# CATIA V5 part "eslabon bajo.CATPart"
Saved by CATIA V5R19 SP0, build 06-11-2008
Part number: eslabon bajo
Material "Dull Blue": density 7860 kg/m3, Young's modulus 2e+11 Pa, Poisson ratio 0.266
Bounding box of the stored display mesh (mm): x 215.134 to 253.234, y -414.1 to 363.3, z 11108.335 to 11348.985
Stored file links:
  E:\Luis\Dropbox\3DIT\Parking\planos\cat 3 dit park8\Cadena\eslabon bajo.CATPart
  E:\Luis\Dropbox\3DIT\Parking\planos\cat 3 dit park8\Cadena\Eslabon de Cadena.........................................CATProduct
  E:\Luis\Dropbox\3DIT\Parking\planos\cat 3 dit park8\Cadena\ensamble unico eslabon.CATProduct
  E:\Luis\Dropbox\3DIT\Parking\planos\cat 3 dit park8\Cadena\Eslabon Bajo Completo.CATProduct
  E:\Luis\Dropbox\3DIT\Parking\planos\cat 3 dit park8\Cadena\EslabonCompleto.CATProduct
  C:\Program Files (x86)\Dassault Systemes\B19\intel_a\startup\materials\Catalog.CATMaterial
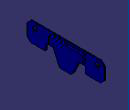
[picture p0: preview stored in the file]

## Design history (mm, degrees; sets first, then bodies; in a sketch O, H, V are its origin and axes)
External parameters (linked from other documents)
  External.p = 625
  External.b1 = 63.5
  External.b2 = 50.8
  External.d2 = 38.1
  External.g = 50.8
Body1 (main body), material "Dull Blue"
  DatumSurface1
  DatumCurve1 to DatumCurve18
  Sketch1 on face of DatumSurface1, origin (253.2342, 0, 0), H (0, -1, 0), V (0, 0, 1)
    line L1 (25.4, 11348.9854) -> (414.1, 11348.9854)
    line L2 (414.1, 11348.9854) -> (414.1, 11158.4854)
    line L3 (223.6, 11228.3354) -> (25.4, 11228.3354)
    point P1 (414.1, 11348.9854)
    point P2 (414.1, 11158.4854)
    line L4 (223.6, 11228.3354) -> (223.6, 11158.4854)
    line L5 (223.6, 11158.4854) -> (414.1, 11158.4854)
    line L6 (414.1, 11158.4854) -> (414.1, 11158.4854)
    point P3 (223.6, 11158.4854)
    point P4 (414.1, 11158.4854)
    construction line L7 (414.1, 11348.9854) -> (223.6, 11158.4854)
    point P5 (223.6, 11228.3354)
    construction line L8 (25.4, 11348.9854) -> (25.4, 11078.9054)
    point P6 (25.4, 11348.9854)
    point P8 (25.4, 11228.3354)
    point P9 (-363.3, 11348.9854)
    point P10 (-363.3, 11158.4854)
    point P11 (-172.8, 11158.4854)
    point P12 (-363.3, 11158.4854)
    construction line L9 (-363.3, 11348.9854) -> (-172.8, 11158.4854)
    point P13 (-172.8, 11228.3354)
    point P14 (25.4, 11348.9854)
    point P15 (25.4, 11228.3354)
    line L10 (25.4, 11348.9854) -> (-363.3, 11348.9854)
    line L11 (-363.3, 11348.9854) -> (-363.3, 11158.4854)
    line L12 (-172.8, 11228.3354) -> (25.4, 11228.3354)
    line L13 (-172.8, 11228.3354) -> (-172.8, 11158.4854)
    line L14 (-172.8, 11158.4854) -> (-363.3, 11158.4854)
    line L15 (-363.3, 11158.4854) -> (-363.3, 11158.4854)
    circle A1 centre (-287.1, 11298.1854) radius 19.05
    circle A2 centre (337.9, 11298.1854) radius 19.05
    point P16 (-287.1, 11298.1854)
    point P17 (337.9, 11298.1854)
    construction line L16 (337.9, 11298.1854) -> (-287.1, 11298.1854)
    radius A2 = 19.05 {= External.d2 /2000}
    distance A2 L2 = 57.15 {= Sketch1.distance(L11 A1)}
    distance A1 L3 = 50.8 {= Sketch1.distance(P17 L1)}
    angle L7 L5 = 45
    length L5 = 190.5 {= External.d2 *5/1000}
    length L11 = 190.5 {= Sketch1.length(L5)}
    distance L11 A1 = 57.15 {= External.d2 *1.5/1000}
    radius A1 = 19.05 {= External.d2/2 /1000}
    distance P16 L8 = 312.5 {= External.p /2000}
    distance P2 H = 11158.4854
    distance L11 V = 363.3
    distance P17 L8 = 312.5 (reference)
    distance P17 L1 = 50.8 {= External.g /1000}
    horizontal: L1 H, L3 H, L5 H, L16 H
    vertical: L2 V, L4 V, L6 V, L8 V
    coincidence: L8 P8
    symmetry: P1 P9 L8, P2 P10 L8, P3 P11 L8, P4 P12 L8, L7 L9 L8, P5 P13 L8, P6 P14 L8, P8 P15 L8, L1 L10 L8, L2 L11 L8, L3 L12 L8, L4 L13 L8, L5 L14 L8, L6 L15 L8
    concentricity: P16 A1, P17 A2
  Pad1: profile Sketch1, direction (-1, 0, 0), length 38.1, opposite side length -25.4
  DatumCurve19 to DatumCurve31
  Sketch2 on start face of Pad1, origin (227.8342, 0, 0), H (0, 1, 0), V (0, 0, 1)
    point P1 (0, 11108.3354)
    line L1 (0, 11108.3354) -> (60, 11108.3354)
    point P2 (60, 11108.3354)
    line L2 (60, 11108.3354) -> (123.6615, 11247.2304)
    point P3 (115, 11228.3329)
    line L3 (123.6615, 11247.2304) -> (123.6615, 11329.9354)
    point P4 (123.6615, 11329.9354)
    line L4 (123.6615, 11329.9354) -> (0, 11329.9354)
    point P5 (0, 11329.9354)
    construction line L5 (0, 11463.76) -> (0, 11058.4)
    point P6 (0, 11463.76)
    reference projected line E1 (-273.1, 11348.9854) -> (273.1, 11348.9854) from edge [start face of Pad1 | face of Pad1 from Sketch1.L1]
    reference projected line E2 (-593.6177, 11109.2854) -> (-745.0129, 11109.2854) from edge of DatumCurve19
    reference projected line E3 (-832.0978, 10989.2854) -> (-876.0554, 10989.2854) from edge of DatumCurve20
    reference projected line E4 (273.1, 11228.3354) -> (-273.1, 11228.3354) from edge [start face of Pad1 | face of Pad1 from Sketch1.L3]
    reference projected arc E5 centre (-1007.0978, 11084.2854) radius 25 from (-984.3712, 11094.7017) to (-1007.0978, 11109.2854) ccw from edge of DatumCurve23
    reference projected arc E6 centre (-745.0129, 11084.2854) radius 25 from (-745.0129, 11109.2854) to (-767.7395, 11094.7017) ccw from edge of DatumCurve24
    point P12 (-745.0129, 11084.2854)
    point P13 (-1007.0978, 11084.2854)
    reference projected line E7 (-767.7395, 11094.7017) -> (-809.3712, 11003.869) from edge of DatumCurve25
    reference projected line E8 (-593.6177, 11109.2854) -> (-745.0129, 11109.2854) from edge of DatumCurve26
    reference projected line E9 (-942.7395, 11003.869) -> (-984.3712, 11094.7017) from edge of DatumCurve27
    reference projected line E10 (-1007.0978, 11109.2854) -> (-1158.4931, 11109.2854) from edge of DatumCurve28
    construction line L6 (-809.3712, 11003.869) -> (-730.157, 11176.7)
    point P22 (-730.157, 11176.7)
    construction line L7 (-637.19, 11109.2854) -> (-761.0554, 11109.2854)
    point P23 (-637.19, 11109.2854)
    construction line L8 (-1092.08, 11109.2854) -> (-1006.3433, 11109.2854)
    point P24 (-1092.08, 11109.2854)
    construction line L9 (-990.62, 11108.3354) -> (-1126.2427, 11116.5297)
    point P25 (-990.62, 11108.3354)
    point P27 (-761.0554, 11109.2854)
    point P28 (-1006.3433, 11109.2854)
    reference projected line E11 (-832.0978, 10989.2854) -> (-876.0554, 10989.2854) from edge of DatumCurve29
    construction line L10 (-1019.9583, 11172.3462) -> (-916.076, 10945.6939)
    point P29 (-1019.9583, 11172.3462)
    construction line L11 (-788.5554, 11049.2854) -> (-845.87, 10950.31)
    point P31 (-788.5554, 11049.2854)
    construction line L12 (-788.5554, 11049.2854) -> (-836.0348, 10945.6939)
    point P33 (-836.0348, 10945.6939)
    construction line L13 (-836.0348, 10945.6939) -> (-916.076, 10945.6939)
    point P34 (-836.0348, 10945.6939)
    reference projected line E12 (-832.0978, 10989.2854) -> (-876.0554, 10989.2854) from edge of DatumCurve30
    construction line L14 (-974.5584, 10989.2854) -> (-936.0554, 10989.2854)
    point P37 (-974.5584, 10989.2854)
    point P38 (-936.0554, 10989.2854)
    construction line L15 (-876.0554, 10989.2854) -> (-816.0554, 10989.2854)
    point P39 (-816.0554, 10989.2854)
    reference projected circle E13 centre (-641.0554, 11209.2854) radius 12.7 from edge of DatumCurve31
    point P40 (-641.0554, 11209.2854)
    reference projected circle E14 centre (-337.9, 11298.1854) radius 19.05 from edge [face of Pad1 from Sketch1.A2 | start face of Pad1]
    point P41 (-337.9, 11298.1854)
    point P42 (0, 11329.9354)
    point P43 (-123.6615, 11329.9354)
    line L16 (-123.6615, 11329.9354) -> (0, 11329.9354)
    line L17 (-123.6615, 11247.2304) -> (-123.6615, 11329.9354)
    point P44 (-115, 11228.3329)
    point P45 (-60, 11108.3354)
    line L18 (-60, 11108.3354) -> (-123.6615, 11247.2304)
    point P46 (0, 11108.3354)
    line L19 (0, 11108.3354) -> (-60, 11108.3354)
    point P48 (123.6615, 11247.2304)
    reference projected line E15 (-273.1, 11348.9854) -> (273.1, 11348.9854) from edge [start face of Pad1 | face of Pad1 from Sketch1.L1]
    reference projected line E16 (285.8, 11158.4854) -> (167.8, 11158.4854) from edge [start face of Pad1 | face of Pad1 from Sketch1.L14]
    distance L4 E1 = 19.05
    distance E2 E3 = 120 (reference)
    distance E4 L1 = 120
    distance P27 E11 = 120 (reference)
    distance P28 P27 = 245.2879 (reference)
    distance P3 L5 = 115
    distance P39 P38 = 120 (reference)
    length L1 = 60
    distance P40 L7 = 100
    distance P48 E15 = 101.7549
    angle L6 L7 = 114.6236 (reference)
    angle L2 E16 = 114.624
    coincidence: P1 V, P6 V, P5 L5, P22 E7, P23 E8, P24 E10, P25 L1, P25 E9, L6 P27, L9 P28, P29 E9, P34 P33, L10 E9, P37 E12, L10 P38, L14 L15, L12 P39, P44 L18, P3 L2, P1 P46, P5 P42
    horizontal: L1 H, L4 H, L13 H, L14 H, L15 H
    vertical: L3 V, L5 V
    concentricity: P12 E6, P13 E5, P40 E13, P41 E14
    tangency: L7 E5, L8 E6, L9 E5, L10 E5, L12 E6
    midpoint: P31 E7
    symmetry: P5 P42 L5, P4 P43 L5, L4 L16 L5, L3 L17 L5, P3 P44 L5, P2 P45 L5, L2 L18 L5, P1 P46 L5, L1 L19 L5
  Pad2: profile Sketch2, direction (1, 0, 0), length 25.4
  Sketch3 on end face of Pad2, origin (253.2342, 0, 0), H (0, 1, 0), V (0, 0, 1)
    line L1 (173.6615, 11329.9354) -> (-173.6615, 11329.9354)
    line L2 (-173.6615, 11329.9354) -> (-173.6615, 11253.7354)
    line L3 (-173.6615, 11253.7354) -> (173.6615, 11253.7354)
    line L4 (173.6615, 11253.7354) -> (173.6615, 11329.9354)
    reference projected line E1 (114.9301, 11329.9354) -> (0, 11329.9354) from edge [face of Pad2 from Sketch2.L4 | end face of Pad2]
    reference projected line E2 (123.6615, 11158.3304) -> (123.6615, 11241.0354) from edge [face of Pad2 from Sketch2.L3 | end face of Pad2]
    reference projected line E3 (-123.6615, 11241.0354) -> (-123.6615, 11158.3304) from edge [face of Pad2 from Sketch2.L17 | end face of Pad2]
    reference projected line E4 (0, 11228.3354) -> (-167.8, 11228.3354) from edge [start face of Pad1 | face of Pad1 from Sketch1.L3]
    distance L1 E1 = 0
    distance L4 E2 = 50
    distance L2 E3 = 50
    distance L3 E4 = 25.4
    horizontal: L1 H, L3 H
    vertical: L2 V, L4 V
  Pad3: profile Sketch3, direction (1, 0, 0), up to start face of Pad1
  Chamfer1: length 38.1 {= External.d2 /1000}, angle 45, on edge [face of Pad1 from Sketch1.L1 | face of Pad1 from Sketch1.L2]; edge [face of Pad1 from Sketch1.L11 | face of Pad1 from Sketch1.L10]; edge [face of Pad1 from Sketch1.L2 | face of Pad1 from Sketch1.L5]; edge [face of Pad1 from Sketch1.L14 | face of Pad1 from Sketch1.L11]
  Chamfer2: length 9.525 {= External.d2 /4000}, angle 45, on edge [face of Pad1 from Sketch1.L5 | face of Pad1 from Sketch1.L4]; edge [face of Pad1 from Sketch1.L13 | face of Pad1 from Sketch1.L14]
  DatumSurface2
  Fillet1: radius 25, on edge [face of Pad2 from Sketch2.L19 | face of Pad2 from Sketch2.L18]; edge [face of Pad2 from Sketch2.L2 | face of Pad2 from Sketch2.L1]
  DatumSurface3
  DatumSurface4
  Sketch4 on DatumSurface4, origin (265.9342, -1.3635, 0.5939), H (0, -1, 0), V (0, 0, 1)
    reference projected curve E1 from edge [end face of Pad1 | face of Pad1 from Sketch1.A2]
    construction line L1 (333.204, 11278.8442) -> (333.204, 11278.8442)
    point P1 (333.204, 11278.8442)
    point P2 (333.204, 11278.8442)
    construction line L2 (333.2009, 11278.8448) -> (333.2009, 11278.8448)
    point P3 (333.2009, 11278.8448)
    point P4 (333.2009, 11278.8448)
    construction line L3 (333.204, 11232.9924) -> (372.8557, 11243.79)
    point P5 (333.204, 11232.9924)
    point P7 (333.204, 11232.9924)
    coincidence: P1 E1, P2 E1, P3 E1, P4 E1, P7 P5
    vertical: L1 V
    horizontal: L2 H
    midpoint: P5 L1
